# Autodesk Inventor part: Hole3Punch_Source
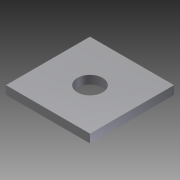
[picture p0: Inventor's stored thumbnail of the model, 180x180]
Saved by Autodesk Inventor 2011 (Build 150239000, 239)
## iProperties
Created: 2007-02
Part Number: Hole3Punch_Source
Material: Default
Document SubType Name: Sheet Metal
Designer: Autodesk, Inc.
Mass: 0.0929314 g
Surface Area: 2.35288 cm^2
Volume: 0.0929314 cm^3
Density: 1 g/cm^3
Sheet Metal Rule: 1 mm
Author: Autodesk, Inc.
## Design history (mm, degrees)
node "Face1"
  sketch "Sketch1"
    geometry: L1 (-5, 5)-(5, 5); L2 (5, 5)-(5, -5); L3 (5, -5)-(-5, -5); L4 (-5, -5)-(-5, 5); L5 (-5, 5)-(5, -5); 2 further points
    constraints: 10 end point, 2 parallel, 1 coincident, 1 horizontal, 1 midpoint, 1 perpendicular
    dimensions: "d0" = 10 distance of L2.end L3.end; "d1" = 10 distance of L1.end L2.end (= d0)
sketch "Sketch2"
  geometry: C1 r 1.5 at (0, 0); 2 further points
  constraints: 2 coincident, 1 centre point
  dimensions: "d3" = 3 diameter of C1
cut "Cut1" sketch "Sketch2" dims "d4" = 1 (= Thickness), "d5" = 0
body "Solid1"
face "Plate1" dims "Thickness" = 1
other parameters: "BendRadius" = 0.5, "BendReliefWidth" = 1 (= Thickness), "BendReliefDepth" = 0.5 (= 0.5 x Thickness), "CornerReliefSize" = 4 (= 4 x Thickness), "SeamGap" = 0.01, "MinimumRemnant" = 2 (= 2 x Thickness), "TransitionRadius" = 0.5 (= BendRadius), "JacobiRadiusSize" = 1 (= Thickness), "d2" = 0.5 (= BendRadius), "GapSize" = 1 (= Thickness)
